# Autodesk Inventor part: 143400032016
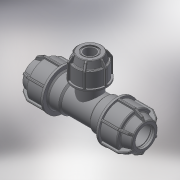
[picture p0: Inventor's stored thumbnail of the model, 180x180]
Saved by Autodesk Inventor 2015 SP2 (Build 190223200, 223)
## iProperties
Created: 2017-08
Part Number: 143400032016
Material: Generic
Description: PLASSON L.14 TEE REDUCER (SILVER) 32-16-32
Document SubType Name: Modeling
Designer: KIM
Density: 1 g/cm^3
Appearance: Default
Author: KIM
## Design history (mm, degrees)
derived "143400.ipt"
feature "Solid1::143400.ipt"
feature "Solid2::143400.ipt"
tag "TaggingFeature1"
body "Solid1"
body "Solid2"
other parameters: "d1" = 32, "d2" = 56, "d4" = 15 deg, "d5" = 36.96, "d6" = 12.1968, "d10" = 61, "d16" = 32.64, "d17" = 2.8, "d22" = 51.2, "d24" = 2.8, "d25" = 54.9, "d26" = 45.75, "d27" = 2.8, "d28" = 135 deg, "d29" = 1.68, "d31" = 1.6, "d46" = 150 deg, "d49" = 3.05, "d50" = 0, "d58" = 0.96, "d61" = 360 deg, "d63" = 28.8, "d64" = 75, "d80" = 46.08, "d81" = 2.56, "d84" = 2.8, "d94" = 54, "d108" = 0.96, "d111" = 0, "d113" = 11.2, "d114" = 34, "d115" = 17, "d116" = 1.7, "d118" = 27, "d119" = 8.1, "d120" = 30.6, "d121" = 26.52, "d122" = 13 deg, "d123" = 16, "d124" = 0.54, "d125" = 1.62, "d126" = 17.6, "d127" = 13.6, "d128" = 22.4, "d129" = 15 deg, "d130" = 3.05, "d131" = 0, "d132" = 1.6, "d133" = 0.32, "d135" = 360 deg, "d_" = 32, "d_1" = 16, "E_" = 61, "l_" = 56, "l_2" = 17, "A_" = 54, "E_1" = 34
